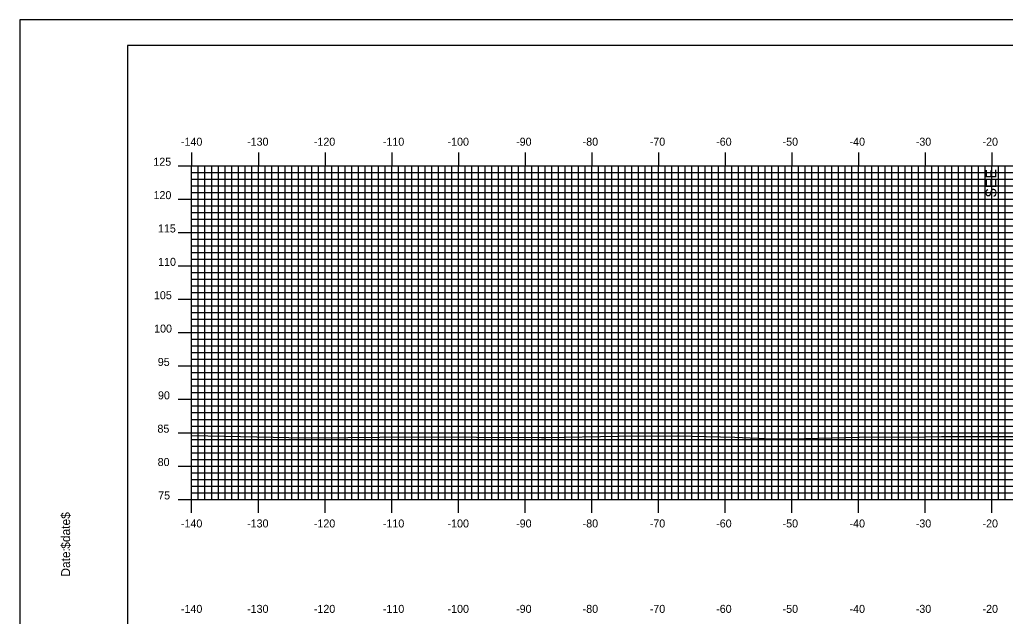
# Model space of a CAD drawing. Extents: x 855690 to 856034, y 364366 to 364586.
# Drawn here: x 855690.5 to 855838.3, y 364496.3 to 364585.7 of the extents above; entities that cross this region are included whole.
import ezdxf

# ---------------------------------------------------------------- set-up
doc = ezdxf.new("R2010")
doc.units = 0
for name, color, linetype in [('ANNOTATION', 7, 'Continuous'), ('BORDER', 7, 'Continuous'), ('H_V ANNOTATION', 7, 'Continuous'), ('MAJOR', 7, 'Continuous'), ('MINOR', 7, 'Continuous'), ('PLOT BOUNDARY', 7, 'Continuous'), ('S_Roadway_Centerline', 7, 'Continuous')]:
    doc.layers.add(name, color=color, linetype=linetype)

msp = doc.modelspace()

# ---------------------------------------------------------------- linework, layer by layer
at = {"layer": 'BORDER'}
msp.add_lwpolyline([(855706.68, 364371.79), (856026.68, 364371.79), (856026.68, 364581.79), (855706.68, 364581.79)], close=True, dxfattribs=at)
at = {"layer": 'MAJOR'}
for p, q in [((855716.28, 364565.79), (855716.28, 364563.79)), ((855726.28, 364565.79), (855726.28, 364563.79)), ((855736.28, 364565.79), (855736.28, 364563.79)), ((855746.28, 364565.79), (855746.28, 364563.79)), ((855756.28, 364565.79), (855756.28, 364563.79)), ((855766.28, 364565.79), (855766.28, 364563.79)), ((855776.28, 364565.79), (855776.28, 364563.79)), ((855786.28, 364565.79), (855786.28, 364563.79)), ((855796.28, 364565.79), (855796.28, 364563.79)), ((855806.28, 364565.79), (855806.28, 364563.79)), ((855816.28, 364565.79), (855816.28, 364563.79)), ((855826.28, 364565.79), (855826.28, 364563.79)), ((855836.28, 364565.79), (855836.28, 364563.79)), ((855714.28, 364563.79), (855716.28, 364563.79)), ((855716.28, 364563.79), (855996.28, 364563.79)), ((855716.28, 364513.79), (855716.28, 364563.79)), ((855716.28, 364513.79), (855716.28, 364563.79)), ((855716.28, 364563.79), (855996.28, 364563.79)), ((855726.28, 364513.79), (855726.28, 364563.79)), ((855736.28, 364513.79), (855736.28, 364563.79)), ((855746.28, 364513.79), (855746.28, 364563.79)), ((855756.28, 364513.79), (855756.28, 364563.79)), ((855766.28, 364513.79), (855766.28, 364563.79)), ((855776.28, 364513.79), (855776.28, 364563.79)), ((855786.28, 364513.79), (855786.28, 364563.79)), ((855796.28, 364513.79), (855796.28, 364563.79)), ((855806.28, 364513.79), (855806.28, 364563.79)), ((855816.28, 364513.79), (855816.28, 364563.79)), ((855826.28, 364513.79), (855826.28, 364563.79)), ((855836.28, 364513.79), (855836.28, 364563.79)), ((855714.28, 364558.79), (855716.28, 364558.79)), ((855716.28, 364558.79), (855996.28, 364558.79)), ((855714.28, 364553.79), (855716.28, 364553.79)), ((855716.28, 364553.79), (855996.28, 364553.79)), ((855714.28, 364548.79), (855716.28, 364548.79)), ((855716.28, 364548.79), (855996.28, 364548.79)), ((855714.28, 364543.79), (855716.28, 364543.79)), ((855716.28, 364543.79), (855996.28, 364543.79)), ((855714.28, 364538.79), (855716.28, 364538.79)), ((855716.28, 364538.79), (855996.28, 364538.79)), ((855714.28, 364533.79), (855716.28, 364533.79)), ((855716.28, 364533.79), (855996.28, 364533.79)), ((855714.28, 364528.79), (855716.28, 364528.79)), ((855716.28, 364528.79), (855996.28, 364528.79)), ((855714.28, 364523.79), (855716.28, 364523.79)), ((855716.28, 364523.79), (855996.28, 364523.79)), ((855714.28, 364518.79), (855716.28, 364518.79)), ((855716.28, 364518.79), (855996.28, 364518.79)), ((855714.28, 364513.79), (855716.28, 364513.79)), ((855716.28, 364513.79), (855996.28, 364513.79)), ((855716.28, 364513.79), (855996.28, 364513.79)), ((855716.28, 364511.78), (855716.28, 364513.79)), ((855726.28, 364511.78), (855726.28, 364513.79)), ((855736.28, 364511.78), (855736.28, 364513.79)), ((855746.28, 364511.78), (855746.28, 364513.79)), ((855756.28, 364511.78), (855756.28, 364513.79)), ((855766.28, 364511.78), (855766.28, 364513.79)), ((855776.28, 364511.78), (855776.28, 364513.79)), ((855786.28, 364511.78), (855786.28, 364513.79)), ((855796.28, 364511.78), (855796.28, 364513.79)), ((855806.28, 364511.78), (855806.28, 364513.79)), ((855816.28, 364511.78), (855816.28, 364513.79)), ((855826.28, 364511.78), (855826.28, 364513.79)), ((855836.28, 364511.78), (855836.28, 364513.79))]:
    msp.add_line(p, q, dxfattribs=at)
at = {"layer": 'MINOR'}
for p, q in [((855717.28, 364513.79), (855717.28, 364563.79)), ((855718.28, 364513.79), (855718.28, 364563.79)), ((855719.28, 364513.79), (855719.28, 364563.79)), ((855720.28, 364513.79), (855720.28, 364563.79)), ((855721.28, 364513.79), (855721.28, 364563.79)), ((855722.28, 364513.79), (855722.28, 364563.79)), ((855723.28, 364513.79), (855723.28, 364563.79)), ((855724.28, 364513.79), (855724.28, 364563.79)), ((855725.28, 364513.79), (855725.28, 364563.79)), ((855727.28, 364513.79), (855727.28, 364563.79)), ((855728.28, 364513.79), (855728.28, 364563.79)), ((855729.28, 364513.79), (855729.28, 364563.79)), ((855730.28, 364513.79), (855730.28, 364563.79)), ((855731.28, 364513.79), (855731.28, 364563.79)), ((855732.28, 364513.79), (855732.28, 364563.79)), ((855733.28, 364513.79), (855733.28, 364563.79)), ((855734.28, 364513.79), (855734.28, 364563.79)), ((855735.28, 364513.79), (855735.28, 364563.79)), ((855737.28, 364513.79), (855737.28, 364563.79)), ((855738.28, 364513.79), (855738.28, 364563.79)), ((855739.28, 364513.79), (855739.28, 364563.79)), ((855740.28, 364513.79), (855740.28, 364563.79)), ((855741.28, 364513.79), (855741.28, 364563.79)), ((855742.28, 364513.79), (855742.28, 364563.79)), ((855743.28, 364513.79), (855743.28, 364563.79)), ((855744.28, 364513.79), (855744.28, 364563.79)), ((855745.28, 364513.79), (855745.28, 364563.79)), ((855747.28, 364513.79), (855747.28, 364563.79)), ((855748.28, 364513.79), (855748.28, 364563.79)), ((855749.28, 364513.79), (855749.28, 364563.79)), ((855750.28, 364513.79), (855750.28, 364563.79)), ((855751.28, 364513.79), (855751.28, 364563.79)), ((855752.28, 364513.79), (855752.28, 364563.79)), ((855753.28, 364513.79), (855753.28, 364563.79)), ((855754.28, 364513.79), (855754.28, 364563.79)), ((855755.28, 364513.79), (855755.28, 364563.79)), ((855757.28, 364513.79), (855757.28, 364563.79)), ((855758.28, 364513.79), (855758.28, 364563.79)), ((855759.28, 364513.79), (855759.28, 364563.79)), ((855760.28, 364513.79), (855760.28, 364563.79)), ((855761.28, 364513.79), (855761.28, 364563.79)), ((855762.28, 364513.79), (855762.28, 364563.79)), ((855763.28, 364513.79), (855763.28, 364563.79)), ((855764.28, 364513.79), (855764.28, 364563.79)), ((855765.28, 364513.79), (855765.28, 364563.79)), ((855767.28, 364513.79), (855767.28, 364563.79)), ((855768.28, 364513.79), (855768.28, 364563.79)), ((855769.28, 364513.79), (855769.28, 364563.79)), ((855770.28, 364513.79), (855770.28, 364563.79)), ((855771.28, 364513.79), (855771.28, 364563.79)), ((855772.28, 364513.79), (855772.28, 364563.79)), ((855773.28, 364513.79), (855773.28, 364563.79)), ((855774.28, 364513.79), (855774.28, 364563.79)), ((855775.28, 364513.79), (855775.28, 364563.79)), ((855777.28, 364513.79), (855777.28, 364563.79)), ((855778.28, 364513.79), (855778.28, 364563.79)), ((855779.28, 364513.79), (855779.28, 364563.79)), ((855780.28, 364513.79), (855780.28, 364563.79)), ((855781.28, 364513.79), (855781.28, 364563.79)), ((855782.28, 364513.79), (855782.28, 364563.79)), ((855783.28, 364513.79), (855783.28, 364563.79)), ((855784.28, 364513.79), (855784.28, 364563.79)), ((855785.28, 364513.79), (855785.28, 364563.79)), ((855787.28, 364513.79), (855787.28, 364563.79)), ((855788.28, 364513.79), (855788.28, 364563.79)), ((855789.28, 364513.79), (855789.28, 364563.79)), ((855790.28, 364513.79), (855790.28, 364563.79)), ((855791.28, 364513.79), (855791.28, 364563.79)), ((855792.28, 364513.79), (855792.28, 364563.79)), ((855793.28, 364513.79), (855793.28, 364563.79)), ((855794.28, 364513.79), (855794.28, 364563.79)), ((855795.28, 364513.79), (855795.28, 364563.79)), ((855797.28, 364513.79), (855797.28, 364563.79)), ((855798.28, 364513.79), (855798.28, 364563.79)), ((855799.28, 364513.79), (855799.28, 364563.79)), ((855800.28, 364513.79), (855800.28, 364563.79)), ((855801.28, 364513.79), (855801.28, 364563.79)), ((855802.28, 364513.79), (855802.28, 364563.79)), ((855803.28, 364513.79), (855803.28, 364563.79)), ((855804.28, 364513.79), (855804.28, 364563.79)), ((855805.28, 364513.79), (855805.28, 364563.79)), ((855807.28, 364513.79), (855807.28, 364563.79)), ((855808.28, 364513.79), (855808.28, 364563.79)), ((855809.28, 364513.79), (855809.28, 364563.79)), ((855810.28, 364513.79), (855810.28, 364563.79)), ((855811.28, 364513.79), (855811.28, 364563.79)), ((855812.28, 364513.79), (855812.28, 364563.79)), ((855813.28, 364513.79), (855813.28, 364563.79)), ((855814.28, 364513.79), (855814.28, 364563.79)), ((855815.28, 364513.79), (855815.28, 364563.79)), ((855817.28, 364513.79), (855817.28, 364563.79)), ((855818.28, 364513.79), (855818.28, 364563.79)), ((855819.28, 364513.79), (855819.28, 364563.79)), ((855820.28, 364513.79), (855820.28, 364563.79)), ((855821.28, 364513.79), (855821.28, 364563.79)), ((855822.28, 364513.79), (855822.28, 364563.79)), ((855823.28, 364513.79), (855823.28, 364563.79)), ((855824.28, 364513.79), (855824.28, 364563.79)), ((855825.28, 364513.79), (855825.28, 364563.79)), ((855827.28, 364513.79), (855827.28, 364563.79)), ((855828.28, 364513.79), (855828.28, 364563.79)), ((855829.28, 364513.79), (855829.28, 364563.79)), ((855830.28, 364513.79), (855830.28, 364563.79)), ((855831.28, 364513.79), (855831.28, 364563.79)), ((855832.28, 364513.79), (855832.28, 364563.79)), ((855833.28, 364513.79), (855833.28, 364563.79)), ((855834.28, 364513.79), (855834.28, 364563.79)), ((855835.28, 364513.79), (855835.28, 364563.79)), ((855837.28, 364513.79), (855837.28, 364563.79)), ((855838.28, 364513.79), (855838.28, 364563.79)), ((855716.28, 364562.79), (855996.28, 364562.79)), ((855716.28, 364562.79), (855718.29, 364562.79)), ((855716.28, 364561.79), (855996.28, 364561.79)), ((855716.28, 364561.79), (855718.29, 364561.79)), ((855716.28, 364560.79), (855996.28, 364560.79)), ((855716.28, 364560.79), (855718.29, 364560.79)), ((855716.28, 364559.79), (855996.28, 364559.79)), ((855716.28, 364559.79), (855718.29, 364559.79)), ((855716.28, 364557.79), (855996.28, 364557.79)), ((855716.28, 364557.79), (855718.29, 364557.79)), ((855716.28, 364556.79), (855996.28, 364556.79)), ((855716.28, 364556.79), (855718.29, 364556.79)), ((855716.28, 364555.79), (855996.28, 364555.79)), ((855716.28, 364555.79), (855718.29, 364555.79)), ((855716.28, 364554.79), (855996.28, 364554.79)), ((855716.28, 364554.79), (855718.29, 364554.79)), ((855716.28, 364552.79), (855996.28, 364552.79)), ((855716.28, 364552.79), (855718.29, 364552.79)), ((855716.28, 364551.79), (855996.28, 364551.79)), ((855716.28, 364551.79), (855718.29, 364551.79)), ((855716.28, 364550.79), (855996.28, 364550.79)), ((855716.28, 364550.79), (855718.29, 364550.79)), ((855716.28, 364549.79), (855996.28, 364549.79)), ((855716.28, 364549.79), (855718.29, 364549.79)), ((855716.28, 364547.79), (855996.28, 364547.79)), ((855716.28, 364547.79), (855718.29, 364547.79)), ((855716.28, 364546.79), (855996.28, 364546.79)), ((855716.28, 364546.79), (855718.29, 364546.79)), ((855716.28, 364545.79), (855996.28, 364545.79)), ((855716.28, 364545.79), (855718.29, 364545.79)), ((855716.28, 364544.79), (855996.28, 364544.79)), ((855716.28, 364544.79), (855718.29, 364544.79)), ((855716.28, 364542.79), (855996.28, 364542.79)), ((855716.28, 364542.79), (855718.29, 364542.79)), ((855716.28, 364541.79), (855996.28, 364541.79)), ((855716.28, 364541.79), (855718.29, 364541.79)), ((855716.28, 364540.79), (855996.28, 364540.79)), ((855716.28, 364540.79), (855718.29, 364540.79)), ((855716.28, 364539.79), (855996.28, 364539.79)), ((855716.28, 364539.79), (855718.29, 364539.79)), ((855716.28, 364537.79), (855996.28, 364537.79)), ((855716.28, 364537.79), (855718.29, 364537.79)), ((855716.28, 364536.79), (855996.28, 364536.79)), ((855716.28, 364536.79), (855718.29, 364536.79)), ((855716.28, 364535.79), (855996.28, 364535.79)), ((855716.28, 364535.79), (855718.29, 364535.79)), ((855716.28, 364534.79), (855996.28, 364534.79)), ((855716.28, 364534.79), (855718.29, 364534.79)), ((855716.28, 364532.79), (855996.28, 364532.79)), ((855716.28, 364532.79), (855718.29, 364532.79)), ((855716.28, 364531.79), (855996.28, 364531.79)), ((855716.28, 364531.79), (855718.29, 364531.79)), ((855716.28, 364530.79), (855996.28, 364530.79)), ((855716.28, 364530.79), (855718.29, 364530.79)), ((855716.28, 364529.79), (855996.28, 364529.79)), ((855716.28, 364529.79), (855718.29, 364529.79)), ((855716.28, 364527.79), (855996.28, 364527.79)), ((855716.28, 364527.79), (855718.29, 364527.79)), ((855716.28, 364526.79), (855996.28, 364526.79)), ((855716.28, 364526.79), (855718.29, 364526.79)), ((855716.28, 364525.79), (855996.28, 364525.79)), ((855716.28, 364525.79), (855718.29, 364525.79)), ((855716.28, 364524.79), (855996.28, 364524.79)), ((855716.28, 364524.79), (855718.29, 364524.79)), ((855716.28, 364522.79), (855996.28, 364522.79)), ((855716.28, 364522.79), (855718.29, 364522.79)), ((855716.28, 364521.79), (855996.28, 364521.79)), ((855716.28, 364521.79), (855718.29, 364521.79)), ((855716.28, 364520.79), (855996.28, 364520.79)), ((855716.28, 364520.79), (855718.29, 364520.79)), ((855716.28, 364519.79), (855996.28, 364519.79)), ((855716.28, 364519.79), (855718.29, 364519.79)), ((855716.28, 364517.79), (855996.28, 364517.79)), ((855716.28, 364517.79), (855718.29, 364517.79)), ((855716.28, 364516.79), (855996.28, 364516.79)), ((855716.28, 364516.79), (855718.29, 364516.79)), ((855716.28, 364515.79), (855996.28, 364515.79)), ((855716.28, 364515.79), (855718.29, 364515.79)), ((855716.28, 364514.79), (855996.28, 364514.79)), ((855716.28, 364514.79), (855718.29, 364514.79))]:
    msp.add_line(p, q, dxfattribs=at)
at = {"layer": 'PLOT BOUNDARY'}
msp.add_lwpolyline([(855690.5, 364365.67), (856030.5, 364365.67), (856030.5, 364585.67), (855690.5, 364585.67)], close=True, dxfattribs=at)
at = {"layer": 'S_Roadway_Centerline'}
msp.add_lwpolyline([(855716.28, 364523.35), (855728.52, 364523.1), (855733.18, 364523.03), (855739.68, 364523.08), (855749.24, 364523.15), (855768.75, 364523.08), (855769.14, 364523.09), (855769.37, 364523.09), (855780.31, 364523.26), (855789.12, 364523.33), (855797.73, 364523.14), (855803.49, 364522.89), (855808.14, 364522.9), (855816.37, 364523.12), (855826.28, 364523.18), (855828.74, 364523.2), (855840.05, 364523.23)], dxfattribs=at)

# ---------------------------------------------------------------- texts
at = {"layer": 'ANNOTATION'}
msp.add_text('SEE', height=1.6, rotation=90, dxfattribs=at).set_placement((855836.94, 364559.02))
at = {"layer": 'BORDER'}
for s, p in [('$date$', (855698.05, 364506.4)), ('Date:', (855698.05, 364502.22))]:
    msp.add_text(s, height=1.339, rotation=90, dxfattribs=at).set_placement(p)
at = {"layer": 'H_V ANNOTATION'}
for s, p in [('-140', (855714.67, 364566.79)), ('-130', (855724.59, 364566.79)), ('-120', (855734.6, 364566.79)), ('-110', (855744.95, 364566.79)), ('-100', (855754.65, 364566.79)), ('-90', (855764.93, 364566.79)), ('-80', (855774.91, 364566.79)), ('-70', (855784.97, 364566.79)), ('-60', (855794.93, 364566.79)), ('-50', (855804.89, 364566.79)), ('-40', (855814.93, 364566.79)), ('-30', (855824.86, 364566.79)), ('-20', (855834.87, 364566.79)), ('125', (855710.53, 364563.79)), ('120', (855710.56, 364558.79)), ('115', (855711.22, 364553.79)), ('110', (855711.25, 364548.79)), ('105', (855710.62, 364543.79)), ('100', (855710.65, 364538.79)), ('95', (855711.2, 364533.79)), ('90', (855711.23, 364528.79)), ('85', (855711.15, 364523.79)), ('80', (855711.18, 364518.79)), ('75', (855711.26, 364513.79)), ('-140', (855714.67, 364509.59)), ('-130', (855724.59, 364509.59)), ('-120', (855734.6, 364509.59)), ('-110', (855744.95, 364509.59)), ('-100', (855754.65, 364509.59)), ('-90', (855764.93, 364509.59)), ('-80', (855774.91, 364509.59)), ('-70', (855784.97, 364509.59)), ('-60', (855794.93, 364509.59)), ('-50', (855804.89, 364509.59)), ('-40', (855814.93, 364509.59)), ('-30', (855824.86, 364509.59)), ('-20', (855834.87, 364509.59)), ('-140', (855714.67, 364496.79)), ('-130', (855724.59, 364496.79)), ('-120', (855734.6, 364496.79)), ('-110', (855744.95, 364496.79)), ('-100', (855754.65, 364496.79)), ('-90', (855764.93, 364496.79)), ('-80', (855774.91, 364496.79)), ('-70', (855784.97, 364496.79)), ('-60', (855794.93, 364496.79)), ('-50', (855804.89, 364496.79)), ('-40', (855814.93, 364496.79)), ('-30', (855824.86, 364496.79)), ('-20', (855834.87, 364496.79))]:
    msp.add_text(s, height=1.2, dxfattribs=at).set_placement(p)
at = {"layer": 'MAJOR'}
msp.add_text('-', height=0.012, dxfattribs=at).set_placement((855716.27, 364513.79))

doc.saveas('drawing.dxf')
